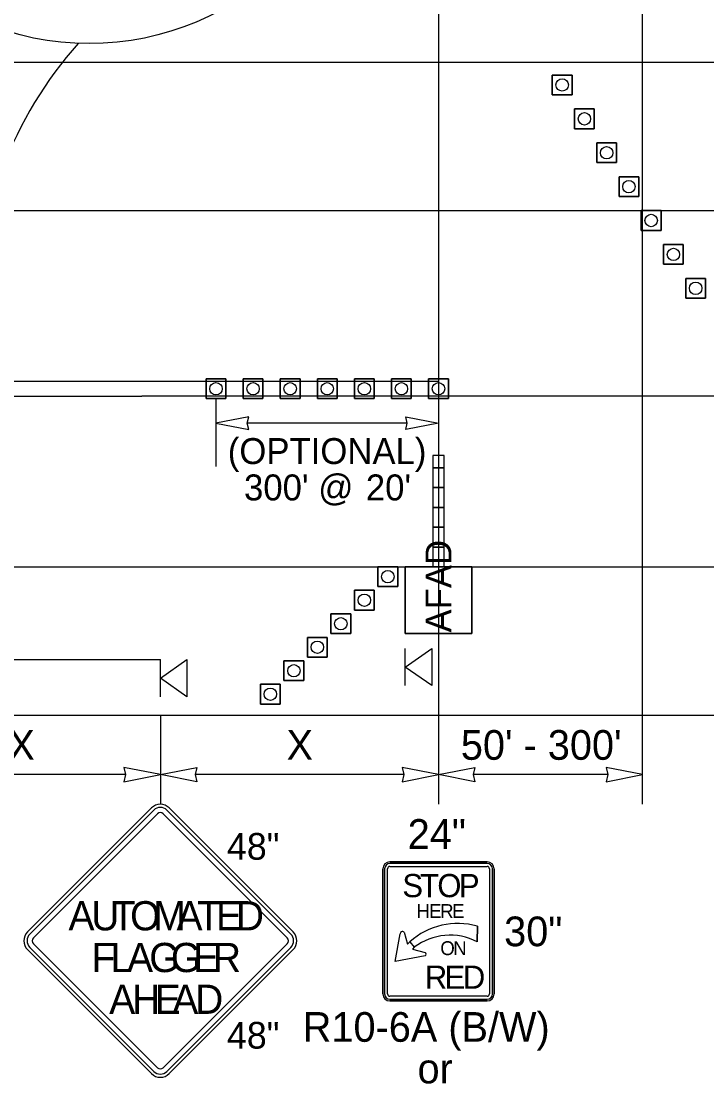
# Model space of a CAD drawing. Extents: x 99999.1 to 100095.7, y 99995 to 100010.7.
# Drawn here: x 100003.152 to 100005, y 100004.739 to 100007.603 of the extents above; entities that cross this region are included whole.
import ezdxf

# ---------------------------------------------------------------- set-up
doc = ezdxf.new("R2010")
doc.units = 0
for name, color, linetype in [('RD_ED_ShoulderPavedEdge', 7, 'Continuous'), ('RD_MK_LineDblYellowCenter', 7, 'Continuous'), ('RD_MK_LineEdgeWhite', 7, 'Continuous'), ('RD_MK_LineNoPass', 7, 'Continuous'), ('RD_MK_LineSkipCenter', 7, 'Continuous'), ('TR_SN_ConstructionSigns', 7, 'Continuous'), ('TR_WZ_AFAD', 7, 'Continuous'), ('TR_WZ_PortableSignMountBlk-Org', 7, 'Continuous'), ('TR_WZ_PortableSignMountBlk-Wht', 7, 'Continuous'), ('TR_WZ_TrafficCone', 7, 'Continuous'), ('TR_WZ_WorkZoneDetails', 7, 'Continuous'), ('TR_WZ_WorkZoneTextCurrent', 7, 'Continuous')]:
    doc.layers.add(name, color=color, linetype=linetype)

msp = doc.modelspace()

# ---------------------------------------------------------------- linework, layer by layer
at = {"layer": 'RD_ED_ShoulderPavedEdge'}
for p, q in [((100000.1076, 100007.4923), (100015.6424, 100007.4923)), ((100000.1076, 100005.7323), (100015.6424, 100005.7323))]:
    msp.add_line(p, q, dxfattribs=at)
at = {"layer": 'RD_MK_LineDblYellowCenter'}
for p, q in [((100000.1282, 100006.6323), (100003.4767, 100006.6323)), ((100000.0869, 100006.5923), (100003.4767, 100006.5923))]:
    msp.add_line(p, q, dxfattribs=at)
at = {"layer": 'RD_MK_LineEdgeWhite'}
for p, q in [((100000.1076, 100007.0923), (100015.6424, 100007.0923)), ((100000.1076, 100006.1323), (100015.6424, 100006.1323))]:
    msp.add_line(p, q, dxfattribs=at)
at = {"layer": 'RD_MK_LineNoPass'}
msp.add_line((100003.4767, 100006.6323), (100004.2767, 100006.6323), dxfattribs=at)
at = {"layer": 'RD_MK_LineSkipCenter'}
msp.add_lwpolyline([(100011.15, 100006.5923), (100003.4767, 100006.5923)], dxfattribs=at)
at = {"layer": 'TR_SN_ConstructionSigns'}
for p, q in [((100003.5028, 100005.4824), (100003.1687, 100005.1483)), ((100003.5088, 100005.4765), (100003.1746, 100005.1424)), ((100003.1846, 100005.1324), (100003.5187, 100005.4665)), ((100003.5346, 100005.4665), (100003.8687, 100005.1324)), ((100003.8787, 100005.1424), (100003.5445, 100005.4765)), ((100003.8846, 100005.1483), (100003.5505, 100005.4824)), ((100004.4079, 100005.3373), (100004.1454, 100005.3373)), ((100004.1454, 100005.3373), (100004.4079, 100005.3373)), ((100004.4079, 100005.3373), (100004.1454, 100005.3373)), ((100004.1454, 100005.3373), (100004.4079, 100005.3373)), ((100004.4079, 100005.3326), (100004.1454, 100005.3326)), ((100004.1454, 100005.3248), (100004.4079, 100005.3248)), ((100004.1267, 100005.3186), (100004.1267, 100004.9811)), ((100004.1267, 100004.9811), (100004.1267, 100005.3186)), ((100004.1267, 100005.3186), (100004.1267, 100004.9811)), ((100004.1267, 100004.9811), (100004.1267, 100005.3186)), ((100004.1313, 100005.3186), (100004.1313, 100004.9811)), ((100004.1392, 100004.9811), (100004.1392, 100005.3186)), ((100004.4142, 100005.3186), (100004.4142, 100004.9811)), ((100004.422, 100004.9811), (100004.422, 100005.3186)), ((100004.4267, 100004.9811), (100004.4267, 100005.3186)), ((100004.4267, 100005.3186), (100004.4267, 100004.9811)), ((100004.4267, 100004.9811), (100004.4267, 100005.3186)), ((100004.4267, 100005.3186), (100004.4267, 100004.9811)), ((100004.3816, 100005.1635), (100004.3813, 100005.1216)), ((100004.3813, 100005.1216), (100004.3816, 100005.1635)), ((100004.1595, 100005.0686), (100004.1731, 100005.143)), ((100004.1839, 100005.1479), (100004.1933, 100005.1154)), ((100004.1933, 100005.1154), (100004.1996, 100005.1218)), ((100004.1996, 100005.1218), (100004.2113, 100005.1069)), ((100004.1996, 100005.1218), (100004.2113, 100005.1069)), ((100003.1687, 100005.1006), (100003.5028, 100004.7665)), ((100003.1746, 100005.1066), (100003.5088, 100004.7725)), ((100003.5187, 100004.7824), (100003.1846, 100005.1165)), ((100003.8687, 100005.1165), (100003.5346, 100004.7824)), ((100003.5445, 100004.7725), (100003.8787, 100005.1066)), ((100003.5505, 100004.7665), (100003.8846, 100005.1006)), ((100004.2113, 100005.1069), (100004.2066, 100005.1021)), ((100004.2066, 100005.1021), (100004.2408, 100005.0929)), ((100004.2406, 100005.0837), (100004.1595, 100005.0686)), ((100004.4079, 100004.9748), (100004.1454, 100004.9748)), ((100004.1454, 100004.967), (100004.4079, 100004.967)), ((100004.1454, 100004.9623), (100004.4079, 100004.9623)), ((100004.4079, 100004.9623), (100004.1454, 100004.9623)), ((100004.1454, 100004.9623), (100004.4079, 100004.9623)), ((100004.4079, 100004.9623), (100004.1454, 100004.9623))]:
    msp.add_line(p, q, dxfattribs=at)
for centre, radius, start, end in [((100003.5267, 100005.4586), 0.0338, 45, 135), ((100003.5267, 100005.4586), 0.0253, 45, 135), ((100003.5267, 100005.4586), 0.0113, 45, 135), ((100004.1454, 100005.3186), 0.0187, 90, 180), ((100004.1454, 100005.3186), 0.0187, 90, 180), ((100004.1454, 100005.3186), 0.0187, 90, 180), ((100004.1454, 100005.3186), 0.0187, 90, 180), ((100004.1454, 100005.3186), 0.0141, 90, 180), ((100004.1454, 100005.3186), 0.00625, 90, 180), ((100004.4079, 100005.3186), 0.0187, 0, 90), ((100004.4079, 100005.3186), 0.0187, 0, 90), ((100004.4079, 100005.3186), 0.0187, 0, 90), ((100004.4079, 100005.3186), 0.0187, 0, 90), ((100004.4079, 100005.3186), 0.0141, 0, 90), ((100004.4079, 100005.3186), 0.00625, 0, 90), ((100004.3279, 100004.9804), 0.1909, 73.6434, 132.2131), ((100004.3279, 100004.9804), 0.1909, 73.6434, 132.2131), ((100003.1925, 100005.1245), 0.0338, 135, 225), ((100003.1925, 100005.1245), 0.0253, 135, 225), ((100003.1925, 100005.1245), 0.0113, 135, 225), ((100003.8608, 100005.1245), 0.0113, 315, 45), ((100003.8608, 100005.1245), 0.0253, 315, 45), ((100003.8608, 100005.1245), 0.0338, 315, 45), ((100004.3078, 100004.981), 0.1586, 62.4149, 127.4769), ((100004.3078, 100004.981), 0.1586, 62.4149, 127.4769), ((100004.1454, 100004.9811), 0.0187, 180, 270), ((100004.1454, 100004.9811), 0.0187, 180, 270), ((100004.1454, 100004.9811), 0.0187, 180, 270), ((100004.1454, 100004.9811), 0.0187, 180, 270), ((100004.1454, 100004.9811), 0.0141, 180, 270), ((100004.1454, 100004.9811), 0.00625, 180, 270), ((100004.4079, 100004.9811), 0.0187, 270, 0), ((100004.4079, 100004.9811), 0.0187, 270, 0), ((100004.4079, 100004.9811), 0.0187, 270, 0), ((100004.4079, 100004.9811), 0.0141, 270, 0), ((100004.4079, 100004.9811), 0.00625, 270, 0), ((100004.4079, 100004.9811), 0.0187, 270, 0), ((100003.5267, 100004.7904), 0.0113, 225, 315), ((100003.5267, 100004.7904), 0.0338, 225, 315), ((100003.5267, 100004.7904), 0.0253, 225, 315)]:
    msp.add_arc(centre, radius, start, end, dxfattribs=at)
for centre, major_axis, ratio, start_param, end_param in [((100004.1795, 100005.1431), (-0.00647, -0.00009), 0.989437, 3.962549, 6.283185), ((100004.2384, 100005.0883), (-0.0046, 0.00239), 0.999053, 2.490568, 4.712389)]:
    msp.add_ellipse(centre, major_axis=major_axis, ratio=ratio, start_param=start_param, end_param=end_param, dxfattribs=at)
at = {"layer": 'TR_WZ_AFAD'}
for p, q in [((100004.2916, 100006.399), (100004.2916, 100006.4323)), ((100004.2616, 100006.399), (100004.2616, 100006.3457)), ((100004.2616, 100006.399), (100004.2766, 100006.399)), ((100004.2766, 100006.399), (100004.2916, 100006.399)), ((100004.2916, 100006.3457), (100004.2916, 100006.399)), ((100004.2616, 100006.3457), (100004.2616, 100006.2923)), ((100004.2766, 100006.3457), (100004.2616, 100006.3457)), ((100004.2916, 100006.3457), (100004.2766, 100006.3457)), ((100004.2916, 100006.2923), (100004.2916, 100006.3457)), ((100004.2616, 100006.2923), (100004.2616, 100006.239)), ((100004.2616, 100006.2923), (100004.2766, 100006.2923)), ((100004.2766, 100006.2923), (100004.2916, 100006.2923)), ((100004.2916, 100006.239), (100004.2916, 100006.2923)), ((100004.2766, 100006.239), (100004.2616, 100006.239)), ((100004.2616, 100006.239), (100004.2616, 100006.1857)), ((100004.2916, 100006.239), (100004.2766, 100006.239)), ((100004.2916, 100006.1857), (100004.2916, 100006.239)), ((100004.2616, 100006.1857), (100004.2616, 100006.1323)), ((100004.1866, 100005.9523), (100004.1866, 100006.1323)), ((100004.1866, 100006.1323), (100004.3666, 100006.1323)), ((100004.27, 100006.1323), (100004.1866, 100006.1323)), ((100004.1866, 100006.1323), (100004.1866, 100005.9523)), ((100004.2616, 100006.1323), (100004.27, 100006.1323)), ((100004.27, 100006.1323), (100004.2766, 100006.1323)), ((100004.3666, 100006.1323), (100004.3666, 100005.9523)), ((100004.3666, 100005.9523), (100004.3666, 100006.1323)), ((100004.3666, 100005.9523), (100004.1866, 100005.9523)), ((100004.1866, 100005.9523), (100004.3666, 100005.9523))]:
    msp.add_line(p, q, dxfattribs=at)
for points in [[(100004.2916, 100006.4323), (100004.2616, 100006.4323), (100004.2616, 100006.399)], [(100004.2916, 100006.1323), (100004.2916, 100006.4323), (100004.2616, 100006.4323), (100004.2616, 100006.1323)], [(100004.2916, 100006.399), (100004.2766, 100006.399), (100004.2616, 100006.399)], [(100004.2616, 100006.3457), (100004.2766, 100006.3457), (100004.2916, 100006.3457)], [(100004.2916, 100006.2923), (100004.2766, 100006.2923), (100004.2616, 100006.2923)], [(100004.2616, 100006.239), (100004.2766, 100006.239), (100004.2916, 100006.239)], [(100004.2916, 100006.1857), (100004.2766, 100006.1857), (100004.2616, 100006.1857)], [(100004.2616, 100006.1857), (100004.2766, 100006.1857), (100004.2916, 100006.1857)], [(100004.2766, 100006.1323), (100004.2833, 100006.1323), (100004.2916, 100006.1323), (100004.2916, 100006.1857)], [(100004.3666, 100006.1323), (100004.2833, 100006.1323), (100004.27, 100006.1323)]]:
    msp.add_lwpolyline(points, dxfattribs=at)
at = {"layer": 'TR_WZ_PortableSignMountBlk-Org'}
msp.add_line((100003.5267, 100005.7824), (100003.5267, 100005.8824), dxfattribs=at)
msp.add_lwpolyline([(100003.5267, 100005.8323), (100003.5985, 100005.8824), (100003.5985, 100005.7824)], close=True, dxfattribs=at)
at = {"layer": 'TR_WZ_PortableSignMountBlk-Wht'}
msp.add_line((100004.1867, 100005.8123), (100004.1867, 100005.9123), dxfattribs=at)
msp.add_lwpolyline([(100004.1867, 100005.8622), (100004.2585, 100005.9123), (100004.2585, 100005.8123)], close=True, dxfattribs=at)
at = {"layer": 'TR_WZ_TrafficCone'}
for points in [[(100004.6367, 100007.4577), (100004.5834, 100007.4577), (100004.5834, 100007.4043), (100004.6367, 100007.4043), (100004.6367, 100007.4577)], [(100004.6367, 100007.4043), (100004.5834, 100007.4043), (100004.5834, 100007.4577), (100004.6367, 100007.4577), (100004.6367, 100007.4043)], [(100004.6967, 100007.3663), (100004.6434, 100007.3663), (100004.6434, 100007.313), (100004.6967, 100007.313), (100004.6967, 100007.3663)], [(100004.6967, 100007.313), (100004.6434, 100007.313), (100004.6434, 100007.3663), (100004.6967, 100007.3663), (100004.6967, 100007.313)], [(100004.7567, 100007.275), (100004.7034, 100007.275), (100004.7034, 100007.2217), (100004.7567, 100007.2217), (100004.7567, 100007.275)], [(100004.7567, 100007.2217), (100004.7034, 100007.2217), (100004.7034, 100007.275), (100004.7567, 100007.275), (100004.7567, 100007.2217)], [(100004.8167, 100007.1837), (100004.7634, 100007.1837), (100004.7634, 100007.1303), (100004.8167, 100007.1303), (100004.8167, 100007.1837)], [(100004.8167, 100007.1303), (100004.7634, 100007.1303), (100004.7634, 100007.1837), (100004.8167, 100007.1837), (100004.8167, 100007.1303)], [(100004.8234, 100007.0923), (100004.8767, 100007.0923), (100004.8767, 100007.039), (100004.8234, 100007.039), (100004.8234, 100007.0923)], [(100004.8234, 100007.039), (100004.8767, 100007.039), (100004.8767, 100007.0923), (100004.8234, 100007.0923), (100004.8234, 100007.039)], [(100004.8834, 100007.001), (100004.9367, 100007.001), (100004.9367, 100006.9477), (100004.8834, 100006.9477), (100004.8834, 100007.001)], [(100004.8834, 100006.9477), (100004.9367, 100006.9477), (100004.9367, 100007.001), (100004.8834, 100007.001), (100004.8834, 100006.9477)], [(100004.9434, 100006.9097), (100004.9967, 100006.9097), (100004.9967, 100006.8563), (100004.9434, 100006.8563), (100004.9434, 100006.9097)], [(100004.9434, 100006.8563), (100004.9967, 100006.8563), (100004.9967, 100006.9097), (100004.9434, 100006.9097), (100004.9434, 100006.8563)], [(100003.7033, 100006.639), (100003.65, 100006.639), (100003.65, 100006.5857), (100003.7033, 100006.5857), (100003.7033, 100006.639)], [(100003.7033, 100006.5857), (100003.65, 100006.5857), (100003.65, 100006.639), (100003.7033, 100006.639), (100003.7033, 100006.5857)], [(100003.8033, 100006.639), (100003.75, 100006.639), (100003.75, 100006.5857), (100003.8033, 100006.5857), (100003.8033, 100006.639)], [(100003.8033, 100006.5857), (100003.75, 100006.5857), (100003.75, 100006.639), (100003.8033, 100006.639), (100003.8033, 100006.5857)], [(100003.9033, 100006.639), (100003.85, 100006.639), (100003.85, 100006.5857), (100003.9033, 100006.5857), (100003.9033, 100006.639)], [(100003.9033, 100006.5857), (100003.85, 100006.5857), (100003.85, 100006.639), (100003.9033, 100006.639), (100003.9033, 100006.5857)], [(100004.0033, 100006.639), (100003.95, 100006.639), (100003.95, 100006.5857), (100004.0033, 100006.5857), (100004.0033, 100006.639)], [(100004.0033, 100006.5857), (100003.95, 100006.5857), (100003.95, 100006.639), (100004.0033, 100006.639), (100004.0033, 100006.5857)], [(100004.1033, 100006.639), (100004.05, 100006.639), (100004.05, 100006.5857), (100004.1033, 100006.5857), (100004.1033, 100006.639)], [(100004.1033, 100006.5857), (100004.05, 100006.5857), (100004.05, 100006.639), (100004.1033, 100006.639), (100004.1033, 100006.5857)], [(100004.2033, 100006.639), (100004.15, 100006.639), (100004.15, 100006.5857), (100004.2033, 100006.5857), (100004.2033, 100006.639)], [(100004.2033, 100006.5857), (100004.15, 100006.5857), (100004.15, 100006.639), (100004.2033, 100006.639), (100004.2033, 100006.5857)], [(100004.3033, 100006.639), (100004.25, 100006.639), (100004.25, 100006.5857), (100004.3033, 100006.5857), (100004.3033, 100006.639)], [(100004.3033, 100006.5857), (100004.25, 100006.5857), (100004.25, 100006.639), (100004.3033, 100006.639), (100004.3033, 100006.5857)], [(100004.1133, 100006.1323), (100004.1667, 100006.1323), (100004.1667, 100006.079), (100004.1133, 100006.079), (100004.1133, 100006.1323)], [(100004.1133, 100006.079), (100004.1667, 100006.079), (100004.1667, 100006.1323), (100004.1133, 100006.1323), (100004.1133, 100006.079)], [(100004.05, 100006.069), (100004.1033, 100006.069), (100004.1033, 100006.0157), (100004.05, 100006.0157), (100004.05, 100006.069)], [(100004.05, 100006.0157), (100004.1033, 100006.0157), (100004.1033, 100006.069), (100004.05, 100006.069), (100004.05, 100006.0157)], [(100003.9867, 100006.0057), (100004.04, 100006.0057), (100004.04, 100005.9523), (100003.9867, 100005.9523), (100003.9867, 100006.0057)], [(100003.9867, 100005.9523), (100004.04, 100005.9523), (100004.04, 100006.0057), (100003.9867, 100006.0057), (100003.9867, 100005.9523)], [(100003.9767, 100005.9423), (100003.9233, 100005.9423), (100003.9233, 100005.889), (100003.9767, 100005.889), (100003.9767, 100005.9423)], [(100003.9767, 100005.889), (100003.9233, 100005.889), (100003.9233, 100005.9423), (100003.9767, 100005.9423), (100003.9767, 100005.889)], [(100003.9133, 100005.879), (100003.86, 100005.879), (100003.86, 100005.8257), (100003.9133, 100005.8257), (100003.9133, 100005.879)], [(100003.9133, 100005.8257), (100003.86, 100005.8257), (100003.86, 100005.879), (100003.9133, 100005.879), (100003.9133, 100005.8257)], [(100003.85, 100005.8157), (100003.7967, 100005.8157), (100003.7967, 100005.7623), (100003.85, 100005.7623), (100003.85, 100005.8157)], [(100003.85, 100005.7623), (100003.7967, 100005.7623), (100003.7967, 100005.8157), (100003.85, 100005.8157), (100003.85, 100005.7623)]]:
    msp.add_lwpolyline(points, dxfattribs=at)
for centre in [(100004.61, 100007.431), (100004.67, 100007.3397), (100004.73, 100007.2483), (100004.79, 100007.157), (100004.85, 100007.0657), (100004.91, 100006.9743), (100004.97, 100006.883), (100003.6767, 100006.6123), (100003.7767, 100006.6123), (100003.8767, 100006.6123), (100003.9767, 100006.6123), (100004.0767, 100006.6123), (100004.1767, 100006.6123), (100004.2767, 100006.6123), (100004.14, 100006.1057), (100004.0767, 100006.0423), (100004.0133, 100005.979), (100003.95, 100005.9157), (100003.8867, 100005.8523), (100003.8233, 100005.789)]:
    msp.add_circle(centre, 0.0167, dxfattribs=at)
at = {"layer": 'TR_WZ_WorkZoneDetails'}
for p, q in [((100004.2767, 100008.7991), (100004.2767, 100005.4923)), ((100004.8267, 100005.4923), (100004.8267, 100007.7323)), ((100003.6767, 100006.5857), (100003.6767, 100006.4023)), ((100004.1923, 100006.5193), (100003.761, 100006.5193)), ((100000.5267, 100005.8824), (100003.5267, 100005.8824)), ((100003.5267, 100005.7323), (100003.5267, 100005.4923)), ((100003.4329, 100005.5723), (100002.8704, 100005.5723)), ((100004.1829, 100005.5723), (100003.6204, 100005.5723)), ((100004.7329, 100005.5723), (100004.3704, 100005.5723))]:
    msp.add_line(p, q, dxfattribs=at)
for points in [[(100003.6767, 100006.5193), (100003.7651, 100006.502), (100003.761, 100006.5193), (100003.7651, 100006.5367)], [(100004.2767, 100006.5193), (100004.1882, 100006.502), (100004.1923, 100006.5193), (100004.1882, 100006.5367)], [(100003.5267, 100005.5723), (100003.4284, 100005.5916), (100003.4329, 100005.5723), (100003.4284, 100005.5531)], [(100003.5267, 100005.5723), (100003.6249, 100005.5916), (100003.6204, 100005.5723), (100003.6249, 100005.5531)], [(100004.2767, 100005.5723), (100004.1784, 100005.5916), (100004.1829, 100005.5723), (100004.1784, 100005.5531)], [(100004.2767, 100005.5723), (100004.3749, 100005.5916), (100004.3704, 100005.5723), (100004.3749, 100005.5531)], [(100004.8267, 100005.5723), (100004.7284, 100005.5916), (100004.7329, 100005.5723), (100004.7284, 100005.5531)]]:
    msp.add_lwpolyline(points, close=True, dxfattribs=at)
msp.add_circle((100003.3346, 100008.2843), 0.742, dxfattribs=at)
msp.add_arc((100004.1081, 100006.8268), 1.0759, 138.2705, 180.3733, dxfattribs=at)

# ---------------------------------------------------------------- texts
at = {"layer": 'TR_SN_ConstructionSigns'}
for s, height, p in [('24"', 0.08, (100004.1936, 100005.3723)), ('48"', 0.072, (100003.7064, 100005.343)), ('30"', 0.08, (100004.4536, 100005.1098)), ('R10-6A (B/W)', 0.08, (100003.9107, 100004.8523)), ('48"', 0.072, (100003.7064, 100004.8339)), ('or', 0.08, (100004.2201, 100004.7403))]:
    msp.add_text(s, height=height, rotation=360, dxfattribs=at).set_placement(p)
for s, height, p in [('S', 0.0625, (100004.1792, 100005.242)), ('T', 0.0625, (100004.2267, 100005.242)), ('O', 0.0625, (100004.2735, 100005.242)), ('P', 0.0625, (100004.3317, 100005.242)), ('A', 0.0787, (100003.279, 100005.1526)), ('U', 0.0787, (100003.3404, 100005.1526)), ('T', 0.0787, (100003.3955, 100005.1526)), ('O', 0.0787, (100003.4451, 100005.1526)), ('M', 0.0787, (100003.5074, 100005.1526)), ('A', 0.0787, (100003.5704, 100005.1526)), ('T', 0.0787, (100003.6255, 100005.1526)), ('E', 0.0787, (100003.6767, 100005.1526)), ('D', 0.0787, (100003.7302, 100005.1526)), ('H', 0.0375, (100004.217, 100005.1858)), ('E', 0.0375, (100004.2515, 100005.1858)), ('R', 0.0375, (100004.2812, 100005.1858)), ('E', 0.0375, (100004.313, 100005.1858)), ('O', 0.0375, (100004.2815, 100005.0858)), ('N', 0.0375, (100004.3164, 100005.0858)), ('F', 0.0787, (100003.3408, 100005.0401)), ('L', 0.0787, (100003.392, 100005.0401)), ('A', 0.0787, (100003.4369, 100005.0401)), ('G', 0.0787, (100003.4967, 100005.0401)), ('G', 0.0787, (100003.555, 100005.0401)), ('E', 0.0787, (100003.6149, 100005.0401)), ('R', 0.0787, (100003.6684, 100005.0401)), ('R', 0.0625, (100004.2399, 100004.9951)), ('E', 0.0625, (100004.293, 100004.9951)), ('D', 0.0625, (100004.3424, 100004.9951)), ('A', 0.0787, (100003.3888, 100004.9276)), ('H', 0.0787, (100003.4503, 100004.9276)), ('E', 0.0787, (100003.5117, 100004.9276)), ('A', 0.0787, (100003.5589, 100004.9276)), ('D', 0.0787, (100003.6204, 100004.9276))]:
    msp.add_text(s, height=height, dxfattribs=at).set_placement(p)
at = {"layer": 'TR_WZ_AFAD'}
msp.add_text('AFAD', height=0.07, rotation=90, dxfattribs=at).set_placement((100004.3116, 100005.9553))
at = {"layer": 'TR_WZ_WorkZoneTextCurrent'}
for s, p in [('(OPTIONAL)', (100003.7085, 100006.4093)), ("300' @", (100003.7523, 100006.3113)), ("20'", (100004.0807, 100006.3113))]:
    msp.add_text(s, height=0.07, dxfattribs=at).set_placement(p)
for s, p in [("50' - 300'", (100004.3369, 100005.6123)), ('X', (100003.1169, 100005.6123)), ('X', (100003.8669, 100005.6123))]:
    msp.add_text(s, height=0.08, rotation=360, dxfattribs=at).set_placement(p)

doc.saveas('drawing.dxf')
